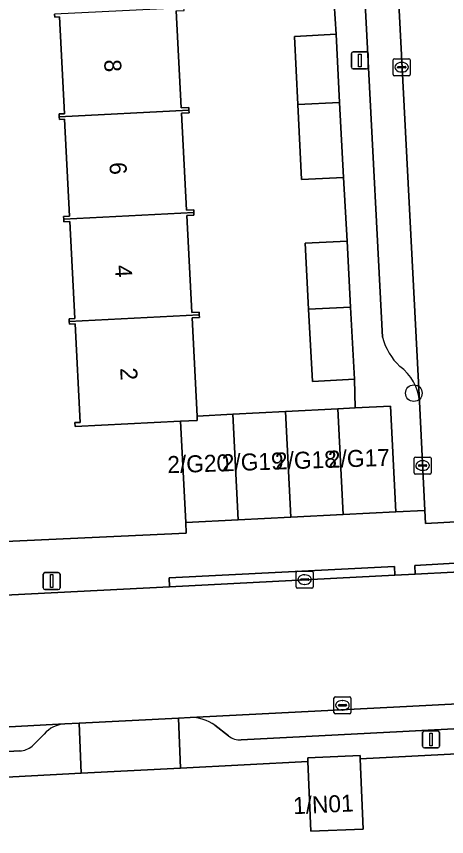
# Model space of a CAD drawing. Extents: x 161084 to 161928, y 385354 to 386522.
# Drawn here: x 161442.17 to 161467.52, y 385436.63 to 385484.89 of the extents above; entities that cross this region are included whole.
import ezdxf

# ---------------------------------------------------------------- set-up
doc = ezdxf.new("R2010")
doc.units = 0
for name, color, linetype in [('IMGEO_Boom', 7, 'Continuous'), ('IMGEO_Erf', 7, 'Continuous'), ('IMGEO_Kolk', 7, 'Continuous'), ('IMGEO_Lichtmast', 7, 'Continuous'), ('IMGEO_Pand', 7, 'Continuous'), ('IMGEO_Pand_nummerreeks', 7, 'Continuous'), ('IMGEO_Parkeervlak_open', 7, 'Continuous'), ('IMGEO_Rijbaan_lokaal_open', 7, 'Continuous'), ('IMGEO_Voetpad_open', 7, 'Continuous')]:
    doc.layers.add(name, color=color, linetype=linetype)

msp = doc.modelspace()

# ---------------------------------------------------------------- linework, layer by layer
at = {"layer": 'IMGEO_Boom'}
msp.add_circle((161465.591, 385462.722), 0.489, dxfattribs=at)
at = {"layer": 'IMGEO_Erf'}
for points in [[(161451.596, 385485.218), (161451.888, 385479.515), (161452.333, 385479.538), (161452.341, 385479.378), (161452.349, 385479.218), (161451.905, 385479.196), (161452.197, 385473.493), (161452.62, 385473.515), (161452.628, 385473.355), (161452.636, 385473.195), (161452.214, 385473.174), (161452.506, 385467.468), (161452.937, 385467.49), (161452.945, 385467.33), (161452.953, 385467.17), (161452.523, 385467.148), (161452.819, 385461.375), (161454.925, 385461.483), (161458.02, 385461.641), (161461.115, 385461.8), (161462.131, 385461.852), (161462.093, 385463.544), (161459.616, 385463.411), (161459.387, 385467.656), (161459.178, 385471.539), (161461.655, 385471.672), (161461.441, 385475.415), (161458.979, 385475.29), (161458.755, 385479.705), (161458.552, 385483.714), (161461.014, 385483.839), (161460.78, 385487.474)], [(161437.255, 385453.799), (161452.179, 385454.491), (161452.148, 385455.111), (161451.843, 385461.069), (161445.636, 385460.751), (161445.624, 385460.987), (161445.929, 385461.003), (161445.633, 385466.8), (161445.299, 385466.783), (161445.291, 385466.943), (161445.283, 385467.103), (161445.616, 385467.12), (161445.325, 385472.822), (161444.971, 385472.804), (161444.962, 385472.964), (161444.954, 385473.124), (161445.309, 385473.142), (161445.017, 385478.844), (161444.709, 385478.828), (161444.701, 385478.988), (161444.693, 385479.148), (161445.001, 385479.164), (161444.709, 385484.866), (161444.435, 385484.852), (161444.427, 385485.012)], [(161531.457, 385435.246), (161530.957, 385444.578), (161522.121, 385444.14), (161514.172, 385443.782), (161506.893, 385443.442), (161489.826, 385442.609), (161472.328, 385441.714), (161462.435, 385441.214), (161462.607, 385437.07), (161459.521, 385436.942), (161459.349, 385441.056), (161451.84, 385440.651), (161445.994, 385440.367), (161427.695, 385439.377), (161410.372, 385438.518), (161399.098, 385437.94), (161399.975, 385420.149)]]:
    msp.add_lwpolyline(points, dxfattribs=at)
at = {"layer": 'IMGEO_Kolk'}
for p, q in [((161464.373, 385481.473), (161464.373, 385482.325)), ((161464.448, 385482.399), (161465.3, 385482.399)), ((161465.374, 385482.325), (161465.374, 385481.473)), ((161464.632, 385481.893), (161464.632, 385481.905)), ((161465.07, 385481.856), (161464.672, 385481.856)), ((161464.675, 385481.942), (161465.073, 385481.942)), ((161464.861, 385482.179), (161464.886, 385482.179)), ((161465.116, 385481.905), (161465.116, 385481.893)), ((161465.3, 385481.399), (161464.448, 385481.399)), ((161464.884, 385481.619), (161464.859, 385481.619)), ((161465.604, 385458.037), (161465.604, 385458.889)), ((161465.679, 385458.963), (161466.531, 385458.963)), ((161466.092, 385458.743), (161466.117, 385458.743)), ((161466.605, 385458.889), (161466.605, 385458.037)), ((161465.863, 385458.457), (161465.863, 385458.469)), ((161466.301, 385458.42), (161465.903, 385458.42)), ((161465.906, 385458.506), (161466.304, 385458.506)), ((161466.347, 385458.469), (161466.347, 385458.457)), ((161466.531, 385457.963), (161465.679, 385457.963)), ((161466.115, 385458.183), (161466.09, 385458.183)), ((161458.659, 385451.327), (161458.659, 385452.179)), ((161458.734, 385452.253), (161459.586, 385452.253)), ((161459.147, 385452.033), (161459.172, 385452.033)), ((161459.66, 385452.179), (161459.66, 385451.327)), ((161458.918, 385451.747), (161458.918, 385451.759)), ((161459.356, 385451.71), (161458.958, 385451.71)), ((161458.961, 385451.796), (161459.359, 385451.796)), ((161459.17, 385451.473), (161459.145, 385451.473)), ((161459.402, 385451.759), (161459.402, 385451.747)), ((161459.586, 385451.253), (161458.734, 385451.253)), ((161460.884, 385443.932), (161460.884, 385444.784)), ((161460.959, 385444.858), (161461.811, 385444.858)), ((161461.885, 385444.784), (161461.885, 385443.932)), ((161461.143, 385444.352), (161461.143, 385444.364)), ((161461.581, 385444.315), (161461.183, 385444.315)), ((161461.186, 385444.401), (161461.584, 385444.401)), ((161461.372, 385444.638), (161461.397, 385444.638)), ((161461.627, 385444.364), (161461.627, 385444.352)), ((161461.811, 385443.858), (161460.959, 385443.858)), ((161461.395, 385444.078), (161461.37, 385444.078))]:
    msp.add_line(p, q, dxfattribs=at)
for points in [[(161464.373, 385481.473), (161464.373, 385482.325)], [(161464.448, 385482.399), (161465.3, 385482.399)], [(161465.374, 385482.325), (161465.374, 385481.473)], [(161465.3, 385481.399), (161464.448, 385481.399)], [(161465.604, 385458.037), (161465.604, 385458.889)], [(161465.679, 385458.963), (161466.531, 385458.963)], [(161466.605, 385458.889), (161466.605, 385458.037)], [(161466.531, 385457.963), (161465.679, 385457.963)], [(161458.659, 385451.327), (161458.659, 385452.179)], [(161458.734, 385452.253), (161459.586, 385452.253)], [(161459.66, 385452.179), (161459.66, 385451.327)], [(161459.586, 385451.253), (161458.734, 385451.253)], [(161460.884, 385443.932), (161460.884, 385444.784)], [(161460.959, 385444.858), (161461.811, 385444.858)], [(161461.885, 385444.784), (161461.885, 385443.932)], [(161461.811, 385443.858), (161460.959, 385443.858)]]:
    msp.add_lwpolyline(points, dxfattribs=at)
for centre, radius, start, end in [((161464.45, 385482.323), 0.0765, 91.552, 178.448), ((161464.45, 385482.323), 0.0765, 91.552, 178.448), ((161465.298, 385482.323), 0.0765, 1.552, 88.448), ((161465.298, 385482.323), 0.0765, 1.552, 88.448), ((161464.672, 385481.902), 0.0403, 85.8775, 175.7526), ((161464.669, 385481.892), 0.0366, 178.938, 274.7102), ((161465.073, 385481.899), 0.043, 264.8664, 352.4533), ((161465.077, 385481.904), 0.0386, 1.7309, 96.639), ((161464.45, 385481.475), 0.0765, 181.552, 268.448), ((161464.45, 385481.475), 0.0765, 181.552, 268.448), ((161465.298, 385481.475), 0.0765, 271.552, 358.448), ((161465.298, 385481.475), 0.0765, 271.552, 358.448), ((161465.681, 385458.887), 0.0765, 91.552, 178.448), ((161465.681, 385458.887), 0.0765, 91.552, 178.448), ((161466.529, 385458.887), 0.0765, 1.552, 88.448), ((161466.529, 385458.887), 0.0765, 1.552, 88.448), ((161465.903, 385458.466), 0.0403, 85.8775, 175.7526), ((161465.9, 385458.456), 0.0366, 178.938, 274.7102), ((161466.304, 385458.463), 0.043, 264.8664, 352.4533), ((161466.308, 385458.468), 0.0386, 1.7309, 96.639), ((161465.681, 385458.039), 0.0765, 181.552, 268.448), ((161465.681, 385458.039), 0.0765, 181.552, 268.448), ((161466.529, 385458.039), 0.0765, 271.552, 358.448), ((161466.529, 385458.039), 0.0765, 271.552, 358.448), ((161458.736, 385452.177), 0.0765, 91.552, 178.448), ((161458.736, 385452.177), 0.0765, 91.552, 178.448), ((161459.584, 385452.177), 0.0765, 1.552, 88.448), ((161459.584, 385452.177), 0.0765, 1.552, 88.448), ((161458.958, 385451.756), 0.0403, 85.8775, 175.7526), ((161458.955, 385451.746), 0.0366, 178.938, 274.7102), ((161459.359, 385451.753), 0.043, 264.8664, 352.4533), ((161459.363, 385451.758), 0.0386, 1.7309, 96.639), ((161458.736, 385451.329), 0.0765, 181.552, 268.448), ((161458.736, 385451.329), 0.0765, 181.552, 268.448), ((161459.584, 385451.329), 0.0765, 271.552, 358.448), ((161459.584, 385451.329), 0.0765, 271.552, 358.448), ((161460.961, 385444.782), 0.0765, 91.552, 178.448), ((161460.961, 385444.782), 0.0765, 91.552, 178.448), ((161461.809, 385444.782), 0.0765, 1.552, 88.448), ((161461.809, 385444.782), 0.0765, 1.552, 88.448), ((161461.183, 385444.361), 0.0403, 85.8775, 175.7526), ((161461.18, 385444.351), 0.0366, 178.938, 274.7102), ((161461.584, 385444.358), 0.043, 264.8664, 352.4533), ((161461.588, 385444.363), 0.0386, 1.7309, 96.639), ((161460.961, 385443.934), 0.0765, 181.552, 268.448), ((161460.961, 385443.934), 0.0765, 181.552, 268.448), ((161461.809, 385443.934), 0.0765, 271.552, 358.448), ((161461.809, 385443.934), 0.0765, 271.552, 358.448)]:
    msp.add_arc(centre, radius, start, end, dxfattribs=at)
for centre, major_axis, ratio, start_param, end_param in [((161464.86, 385481.899), (-0.387, 0.002), 0.722429, 4.712389, 7.853982), ((161464.885, 385481.899), (-0.39, 0.002), 0.717154, 1.570796, 4.712389), ((161466.091, 385458.463), (-0.387, 0.002), 0.722429, 4.712389, 7.853982), ((161466.116, 385458.463), (-0.39, 0.002), 0.717154, 1.570796, 4.712389), ((161459.146, 385451.753), (-0.387, 0.002), 0.722429, 4.712389, 7.853982), ((161459.171, 385451.753), (-0.39, 0.002), 0.717154, 1.570796, 4.712389), ((161461.371, 385444.358), (-0.387, 0.002), 0.722429, 4.712389, 7.853982), ((161461.396, 385444.358), (-0.39, 0.002), 0.717154, 1.570796, 4.712389)]:
    msp.add_ellipse(centre, major_axis=major_axis, ratio=ratio, start_param=start_param, end_param=end_param, dxfattribs=at)
at = {"layer": 'IMGEO_Lichtmast'}
for p, q in [((161461.911, 385481.899), (161461.911, 385482.699)), ((161461.911, 385482.699), (161461.911, 385481.899)), ((161462.011, 385482.799), (161462.801, 385482.799)), ((161462.801, 385482.799), (161462.011, 385482.799)), ((161462.901, 385482.699), (161462.901, 385481.899)), ((161462.901, 385481.899), (161462.901, 385482.699)), ((161462.801, 385481.799), (161462.011, 385481.799)), ((161462.011, 385481.799), (161462.801, 385481.799)), ((161443.754, 385451.269), (161443.754, 385452.069)), ((161443.754, 385452.069), (161443.754, 385451.269)), ((161443.854, 385452.169), (161444.644, 385452.169)), ((161444.644, 385452.169), (161443.854, 385452.169)), ((161444.744, 385452.069), (161444.744, 385451.269)), ((161444.744, 385451.269), (161444.744, 385452.069)), ((161444.644, 385451.169), (161443.854, 385451.169)), ((161443.854, 385451.169), (161444.644, 385451.169)), ((161466.209, 385442.848), (161466.999, 385442.848)), ((161466.999, 385442.848), (161466.209, 385442.848)), ((161466.109, 385441.948), (161466.109, 385442.748)), ((161466.109, 385442.748), (161466.109, 385441.948)), ((161467.099, 385442.748), (161467.099, 385441.948)), ((161467.099, 385441.948), (161467.099, 385442.748)), ((161466.999, 385441.848), (161466.209, 385441.848)), ((161466.209, 385441.848), (161466.999, 385441.848))]:
    msp.add_line(p, q, dxfattribs=at)
for points in [[(161462.331, 385482.674), (161462.481, 385482.674), (161462.481, 385481.924), (161462.331, 385481.924), (161462.331, 385482.674)], [(161444.174, 385452.044), (161444.324, 385452.044), (161444.324, 385451.294), (161444.174, 385451.294), (161444.174, 385452.044)], [(161466.529, 385442.723), (161466.679, 385442.723), (161466.679, 385441.973), (161466.529, 385441.973), (161466.529, 385442.723)]]:
    msp.add_lwpolyline(points, dxfattribs=at)
for centre, start, end in [((161462.011, 385482.699), 90, 180), ((161462.011, 385482.699), 90, 180), ((161462.801, 385482.699), 0, 90), ((161462.801, 385482.699), 360, 90), ((161462.011, 385481.899), 180, 270), ((161462.011, 385481.899), 180, 270), ((161462.801, 385481.899), 270, 0), ((161462.801, 385481.899), 270, 0), ((161443.854, 385452.069), 90, 180), ((161443.854, 385452.069), 90, 180), ((161444.644, 385452.069), 0, 90), ((161444.644, 385452.069), 360, 90), ((161443.854, 385451.269), 180, 270), ((161443.854, 385451.269), 180, 270), ((161444.644, 385451.269), 270, 0), ((161444.644, 385451.269), 270, 0), ((161466.209, 385442.748), 90, 180), ((161466.209, 385442.748), 90, 180), ((161466.999, 385442.748), 0, 90), ((161466.999, 385442.748), 360, 90), ((161466.209, 385441.948), 180, 270), ((161466.209, 385441.948), 180, 270), ((161466.999, 385441.948), 270, 0), ((161466.999, 385441.948), 270, 0)]:
    msp.add_arc(centre, 0.1, start, end, dxfattribs=at)
at = {"layer": 'IMGEO_Pand'}
for points in [[(161451.596, 385485.218), (161452.053, 385485.241), (161452.045, 385485.401), (161444.427, 385485.012), (161444.435, 385484.852), (161444.709, 385484.866), (161445.001, 385479.164), (161444.693, 385479.148), (161444.701, 385478.988), (161452.341, 385479.378), (161452.333, 385479.538), (161451.888, 385479.515)], [(161461.014, 385483.839), (161458.552, 385483.714), (161458.755, 385479.705), (161461.217, 385479.831)], [(161461.217, 385479.831), (161458.755, 385479.705), (161458.979, 385475.29), (161461.441, 385475.415)], [(161451.905, 385479.196), (161452.349, 385479.218), (161452.341, 385479.378), (161444.701, 385478.988), (161444.709, 385478.828), (161445.017, 385478.844), (161445.309, 385473.142), (161444.954, 385473.124), (161444.962, 385472.964), (161452.628, 385473.355), (161452.62, 385473.515), (161452.197, 385473.493)], [(161452.214, 385473.174), (161452.636, 385473.195), (161452.628, 385473.355), (161444.962, 385472.964), (161444.971, 385472.804), (161445.325, 385472.822), (161445.616, 385467.12), (161445.283, 385467.103), (161445.291, 385466.943), (161452.945, 385467.33), (161452.937, 385467.49), (161452.506, 385467.468)], [(161461.655, 385471.672), (161459.178, 385471.539), (161459.387, 385467.656), (161461.865, 385467.781)], [(161461.865, 385467.781), (161459.387, 385467.656), (161459.616, 385463.411), (161462.093, 385463.544)], [(161452.523, 385467.148), (161452.953, 385467.17), (161452.945, 385467.33), (161445.291, 385466.943), (161445.299, 385466.783), (161445.633, 385466.8), (161445.929, 385461.003), (161445.624, 385460.987), (161445.636, 385460.751), (161451.843, 385461.069), (161452.832, 385461.121), (161452.819, 385461.375)], [(161455.243, 385455.269), (161458.338, 385455.428), (161458.02, 385461.641), (161454.925, 385461.483)], [(161458.338, 385455.428), (161461.433, 385455.586), (161461.115, 385461.8), (161458.02, 385461.641)], [(161461.115, 385461.8), (161461.433, 385455.586), (161464.528, 385455.744), (161464.21, 385461.958), (161462.131, 385461.852)], [(161455.243, 385455.269), (161454.925, 385461.483), (161452.819, 385461.375), (161452.832, 385461.121), (161451.843, 385461.069), (161452.148, 385455.111)], [(161462.435, 385441.214), (161462.427, 385441.4), (161459.34, 385441.271), (161459.349, 385441.056), (161459.521, 385436.942), (161462.607, 385437.07)]]:
    msp.add_lwpolyline(points, close=True, dxfattribs=at)
at = {"layer": 'IMGEO_Parkeervlak_open'}
for points in [[(161465.916, 385462.228), (161463.964, 385500), (161462.868, 385521.205)], [(161461.006, 385518.133), (161461.968, 385500), (161463.752, 385466.016)], [(161493.179, 385445.719), (161482.532, 385445.186), (161465.166, 385444.284), (161452.403, 385443.64)], [(161455.423, 385442.331), (161464.942, 385442.818), (161482.561, 385443.727), (161490.174, 385444.101), (161493.265, 385444.259), (161493.179, 385445.719)], [(161445.036, 385443.271), (161432.642, 385442.6), (161432.725, 385441.151), (161442.368, 385441.672)], [(161453.873, 385443.182), (161454.676, 385442.561)], [(161443.095, 385441.956), (161443.802, 385442.657)]]:
    msp.add_lwpolyline(points, dxfattribs=at)
for centre, radius, start, end in [((161467.09, 385466.825), 3.435, 193.6281, 227.3526), ((161463.138, 385462.038), 2.785, 3.9194, 54.2931), ((161445.161, 385441.472), 1.804, 93.9885, 138.9185), ((161452.417, 385441.095), 2.545, 55.0843, 90.3053), ((161455.332, 385443.364), 1.037, 230.7481, 275.0249), ((161442.355, 385442.778), 1.107, 270.6874, 311.9885)]:
    msp.add_arc(centre, radius, start, end, dxfattribs=at)
at = {"layer": 'IMGEO_Rijbaan_lokaal_open'}
msp.add_lwpolyline([(161462.601, 385526.611), (161462.868, 385521.205), (161463.964, 385500), (161465.916, 385462.228), (161466.247, 385455.821), (161466.286, 385455.063), (161468.791, 385455.186), (161471.295, 385455.308), (161471.256, 385456.104), (161470.894, 385463.528), (161469.115, 385500), (161467.943, 385521.882), (161467.675, 385526.897)], dxfattribs=at)
msp.add_lwpolyline([(161492.726, 385453.458), (161492.59, 385453.451), (161486.217, 385453.125), (161473.888, 385452.493), (161472.44, 385452.419), (161465.671, 385452.072), (161464.474, 385452.011), (161451.203, 385451.331), (161432.195, 385450.358), (161432.64, 385442.621), (161432.642, 385442.6), (161445.036, 385443.271), (161445.878, 385443.299), (161451.721, 385443.604), (161452.403, 385443.64), (161465.166, 385444.284), (161482.532, 385445.186), (161493.179, 385445.719)], close=True, dxfattribs=at)
at = {"layer": 'IMGEO_Voetpad_open'}
for points in [[(161463.752, 385466.016), (161461.968, 385500), (161461.006, 385518.133)], [(161460.78, 385487.474), (161461.014, 385483.839), (161461.217, 385479.831), (161461.441, 385475.415), (161461.655, 385471.672), (161461.865, 385467.781), (161462.093, 385463.544), (161462.131, 385461.852), (161464.21, 385461.958), (161464.528, 385455.744), (161466.247, 385455.821), (161465.916, 385462.228)], [(161432.195, 385450.358), (161451.203, 385451.331), (161451.176, 385451.855), (161464.448, 385452.519), (161464.474, 385452.011), (161465.671, 385452.072), (161465.64, 385452.58), (161469.023, 385452.786), (161468.791, 385455.186), (161466.286, 385455.063), (161466.247, 385455.821), (161464.528, 385455.744), (161461.433, 385455.586), (161458.338, 385455.428), (161455.243, 385455.269), (161452.148, 385455.111), (161452.179, 385454.491), (161437.255, 385453.799)], [(161452.403, 385443.64), (161451.721, 385443.604), (161451.84, 385440.651), (161459.349, 385441.056), (161459.34, 385441.271), (161462.427, 385441.4), (161462.435, 385441.214), (161472.328, 385441.714), (161489.826, 385442.609), (161506.893, 385443.442), (161514.172, 385443.782), (161514.056, 385446.768)], [(161510.331, 385445.123), (161500.655, 385444.636), (161496.077, 385444.402), (161493.265, 385444.259), (161490.174, 385444.101), (161482.561, 385443.727), (161464.942, 385442.818), (161455.423, 385442.331)], [(161391.326, 385437.568), (161399.098, 385437.94), (161410.372, 385438.518), (161427.695, 385439.377), (161445.994, 385440.367), (161445.878, 385443.299), (161445.036, 385443.271)], [(161454.676, 385442.561), (161453.873, 385443.182)], [(161443.802, 385442.657), (161443.095, 385441.956)], [(161442.368, 385441.672), (161432.725, 385441.151), (161429.944, 385441.001), (161427.286, 385440.857), (161416.234, 385440.298), (161404.174, 385439.704)]]:
    msp.add_lwpolyline(points, dxfattribs=at)
for points in [[(161472.405, 385452.991), (161469.023, 385452.786), (161465.64, 385452.58), (161465.671, 385452.072), (161472.44, 385452.419)], [(161464.474, 385452.011), (161464.448, 385452.519), (161451.176, 385451.855), (161451.203, 385451.331)], [(161451.721, 385443.604), (161445.878, 385443.299), (161445.994, 385440.367), (161451.84, 385440.651)]]:
    msp.add_lwpolyline(points, close=True, dxfattribs=at)
for centre, radius, start, end in [((161467.09, 385466.825), 3.435, 193.6281, 227.3526), ((161463.138, 385462.038), 2.785, 3.9194, 54.2931), ((161445.161, 385441.472), 1.804, 93.9885, 138.9185), ((161452.417, 385441.095), 2.545, 55.0843, 90.3053), ((161455.332, 385443.364), 1.037, 230.7481, 275.0249), ((161442.355, 385442.778), 1.107, 270.6874, 311.9885)]:
    msp.add_arc(centre, radius, start, end, dxfattribs=at)

# ---------------------------------------------------------------- texts
at = {"layer": 'IMGEO_Pand_nummerreeks'}
for s, rotation, p in [('8', 272.9906, (161447.337, 385482.332)), ('6', 272.9906, (161447.653, 385476.29)), ('4', 272.9906, (161447.969, 385470.243)), ('2', 272.9906, (161448.285, 385464.199)), ('2/G19', 1.9092, (161454.294, 385458.119)), ('2/G18', 1.9092, (161457.426, 385458.223)), ('2/G17', 1.9092, (161460.547, 385458.327)), ('2/G20', 1.9092, (161451.084, 385458.012)), ('1/N01', 2.7273, (161458.499, 385437.946))]:
    msp.add_text(s, height=1, rotation=rotation, dxfattribs=at).set_placement(p)

doc.saveas('drawing.dxf')
